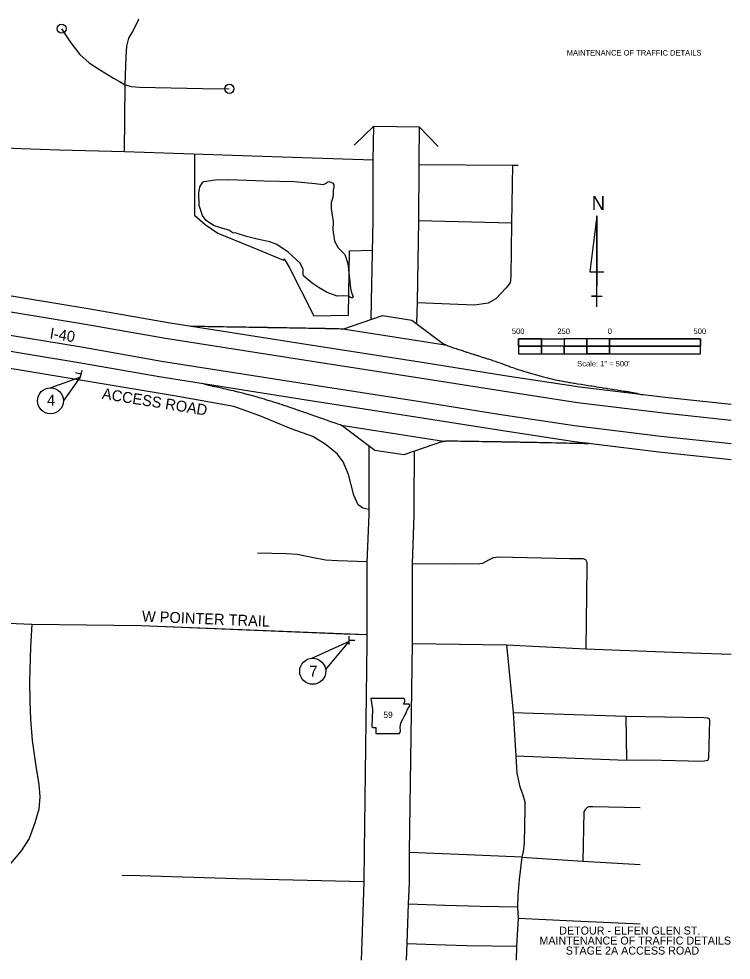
# Model space of a CAD drawing. Extents: x 185625 to 193575, y 1257500 to 1262681.
# Drawn here: x 189658 to 193575, y 1257500 to 1262681 of the extents above; entities that cross this region are included whole.
import ezdxf

# ---------------------------------------------------------------- set-up
doc = ezdxf.new("R2010")
doc.units = 0
for name, color, linetype in [('10', 7, 'Continuous'), ('21', 7, 'Continuous'), ('35', 7, 'Continuous'), ('37', 7, 'Continuous'), ('8', 7, 'Continuous'), ('Level 1', 7, 'Continuous'), ('Level 3', 7, 'Continuous'), ('Level 32', 7, 'Continuous'), ('Level 8', 7, 'Continuous')]:
    doc.layers.add(name, color=color, linetype=linetype)

msp = doc.modelspace()

# ---------------------------------------------------------------- linework, layer by layer
at = {"layer": '10'}
for p, q in [((191440.1, 1260972.6), (191658.4, 1261048)), ((191658.4, 1261048), (191818.5, 1261023.1)), ((191818.5, 1261023.1), (192003.6, 1260885)), ((191721.8, 1260928.8), (191440.1, 1260972.6)), ((192003.6, 1260885), (191721.8, 1260928.8)), ((191615.5, 1260305.5), (191430.5, 1260443.8)), ((191430.5, 1260443.8), (191712.2, 1260399.8)), ((191712.2, 1260399.8), (191993.9, 1260355.8)), ((191993.9, 1260355.8), (191775.6, 1260280.5)), ((191775.6, 1260280.5), (191615.5, 1260305.5))]:
    msp.add_line(p, q, dxfattribs=at)
for points in [[(190239.8, 1261948.5), (190243, 1262317.6), (190247.8, 1262473.6), (190252.5, 1262530.8), (190263.7, 1262573.8), (190284.3, 1262610.4), (190316.2, 1262675.6), (190317.7, 1262680.7)], [(189893.1, 1262626.3), (189944, 1262548.3), (189993.3, 1262484.7), (190045.8, 1262438.6), (190107.8, 1262398.8), (190179.4, 1262354.2), (190211.2, 1262335.1), (190243, 1262317.6)], [(190243, 1262317.6), (190276.4, 1262308.1), (190320.9, 1262304.9), (190667.7, 1262297), (190815.6, 1262295.4)], [(191596.5, 1261026.6), (191598.3, 1261127.6), (191606.9, 1261572), (191607.2, 1261878.7), (191607.1, 1261898.5), (191610.2, 1262090.1)], [(191610.2, 1262090.1), (191860.2, 1262086), (191857.1, 1261897.5), (191857.2, 1261879.7), (191856.9, 1261569.5), (191848.3, 1261122.6), (191845.8, 1261002.7)], [(191607.1, 1261902.2), (190996, 1261923), (190239.8, 1261948.5), (189882, 1261957.3), (189673.6, 1261965.3), (189185.3, 1261986), (188879.9, 1261994.5), (188779.5, 1261996.5), (188563.3, 1262000.1), (188150.6, 1262010.8)], [(190623.5, 1261935.6), (190624.8, 1261599.6), (190682.4, 1261548), (190752.3, 1261501.3), (190973.2, 1261410.5), (191113, 1261352.8), (191116.7, 1261360.2), (191144.9, 1261314.7), (191280.6, 1261046.2), (191471.6, 1261050.4), (191477.4, 1261403.8)], [(192373.6, 1261875.3), (192368.3, 1261555.8), (192364.7, 1261262.5), (192359.3, 1261228.6), (192337.9, 1261200), (192280.7, 1261139.2), (192239.6, 1261116), (192164.6, 1261105.3), (191848.2, 1261118.4)], [(191857.2, 1261878.4), (192373.6, 1261875.3), (192404, 1261875.3)], [(193575.5, 1260557.6), (193212.7, 1260596.5), (192742.7, 1260653.6), (192330.9, 1260716.5), (191888.1, 1260787.1), (191307.8, 1260876.8), (190478.8, 1261007.5), (190038.6, 1261084.8), (189048.5, 1261248.2), (187820.3, 1261444.8), (186840.7, 1261603.3)], [(192368.3, 1261555.8), (191856.9, 1261568.5)], [(186840.7, 1261517.2), (187806.8, 1261360.9), (189034.8, 1261164.3), (190024.3, 1261001), (190464.9, 1260923.6), (191294.7, 1260792.9), (191874.9, 1260703.1), (192317.8, 1260632.5), (192731.2, 1260569.4), (193203.1, 1260512.1), (193575.5, 1260472.1)], [(193575.5, 1260341.4), (193188.3, 1260382.9), (192713.5, 1260440.6), (192297.7, 1260504), (191854.7, 1260574.7), (191274.6, 1260664.4), (190443.5, 1260795.4), (190002.5, 1260872.9), (189014, 1261035.9), (187786.1, 1261232.6), (186840.7, 1261385.5)], [(191477.4, 1261403.8), (191603.8, 1261408.2), (191603.8, 1261408.2)], [(186840.7, 1261299.4), (187772.6, 1261148.7), (189000.3, 1260952), (189988.2, 1260789.1), (190429.5, 1260711.5), (191261.5, 1260580.4), (191841.6, 1260490.7), (192284.6, 1260420), (192702, 1260356.4), (193178.6, 1260298.5), (193575.5, 1260255.9)], [(191582.4, 1259981.2), (191550.8, 1259987.2), (191524.3, 1260006.5), (191500.2, 1260059.6), (191471.2, 1260173), (191442.3, 1260243), (191410.9, 1260284), (191348.2, 1260337.1), (191275.8, 1260382.9), (191155.2, 1260424), (190983.1, 1260495.9), (190840.8, 1260546.5), (190511.6, 1260605.2), (189655.3, 1260749.8), (189036.5, 1260848.7), (188221.1, 1260983.9), (187505.6, 1261095.4), (186840.7, 1261207.7)], [(191443.4, 1260973.7), (191443.3, 1260973.7), (191439.8, 1260973.5), (191432.4, 1260973.6), (191427.9, 1260973.7), (191418.1, 1260974.1), (191407.8, 1260974.5), (191402.2, 1260974.6), (191387.2, 1260974.9), (191372.1, 1260975.1), (191364.6, 1260975.3), (191356.9, 1260975.4), (191344.6, 1260975.5), (191342.1, 1260975.6), (191327.1, 1260975.9), (191324.7, 1260975.9), (191312.1, 1260976.1), (191297.2, 1260976.4), (191282.2, 1260976.7), (191267.1, 1260977), (191252, 1260977.3), (191237, 1260977.5), (191222, 1260977.8), (191192, 1260978.3), (191184.7, 1260978.4), (191177.4, 1260978.5), (191162.3, 1260978.9), (191147.1, 1260979.1), (191132.1, 1260979.3), (191117.3, 1260979.5), (191102.3, 1260979.8), (191087.3, 1260980.1), (191084.8, 1260980.2), (191064.6, 1260980.5), (191057, 1260980.5), (191044.8, 1260980.7), (191042.3, 1260980.7), (191027.4, 1260981), (191024.9, 1260981.1), (191012.3, 1260981.3), (190997.3, 1260981.6), (190982.2, 1260981.8), (190967.1, 1260982.1), (190963.7, 1260982.1), (190952.1, 1260982.2), (190937.2, 1260982.5), (190923.8, 1260982.7), (190907.1, 1260982.9), (190903.7, 1260982.9), (190892.1, 1260983.1), (190877.2, 1260983.3), (190863.8, 1260983.5), (190862.3, 1260983.5), (190832.3, 1260984), (190817.3, 1260984.3), (190802.5, 1260984.5), (190783.1, 1260985), (190772.3, 1260985.2), (190762.9, 1260985.4), (190757.4, 1260985.5), (190742.9, 1260985.7), (190742.2, 1260985.7), (190722.8, 1260986), (190712.3, 1260986.2), (190702.8, 1260986.3), (190697.2, 1260986.4), (190682.3, 1260986.7), (190667.3, 1260987), (190652.1, 1260987.2), (190637.1, 1260987.4), (190622.7, 1260987.6), (190607.1, 1260987.8), (190606.4, 1260987.8), (190603.6, 1260987.8)], [(191992.2, 1260893.4), (191997.2, 1260890.5), (191998.8, 1260889.5), (192006.2, 1260885.7), (192017.7, 1260881.1), (192033.4, 1260875.4), (192046.9, 1260870.7), (192048.6, 1260870.1), (192062.9, 1260865.5), (192067.6, 1260863.9), (192077.6, 1260860.8), (192091.7, 1260856.3), (192105.6, 1260851.7), (192106.1, 1260851.6), (192120.4, 1260847), (192124.8, 1260845.7), (192143.7, 1260839.6), (192162.7, 1260833.4), (192163.5, 1260833.2), (192177.8, 1260828.6), (192181.8, 1260827.3), (192200.9, 1260821.2), (192219.8, 1260815.2), (192220.5, 1260815), (192234.7, 1260810.4), (192238.6, 1260809.1), (192262.1, 1260801.3), (192262.9, 1260801.1), (192276.9, 1260796.4), (192290.7, 1260791.6), (192304.5, 1260786.7), (192317.7, 1260781.9), (192318.6, 1260781.6), (192332.7, 1260776.5), (192336.7, 1260775.1), (192355.5, 1260768.3), (192361, 1260766.3), (192375.5, 1260761.2), (192393.9, 1260754.9), (192404.2, 1260751.4), (192418.7, 1260746.5), (192432.7, 1260742), (192433.9, 1260741.6), (192447.9, 1260737.3), (192452.2, 1260736), (192472.9, 1260730), (192477.7, 1260728.7), (192492.1, 1260724.6), (192492.2, 1260724.6), (192511.4, 1260719.2), (192531, 1260713.7), (192535.9, 1260712.4), (192550.6, 1260708.4), (192565.5, 1260704.7), (192570.7, 1260703.3), (192580.5, 1260701), (192590.1, 1260698.6), (192595.1, 1260697.5), (192609.7, 1260694.2), (192610.5, 1260694), (192625.6, 1260691), (192630.7, 1260690), (192640.3, 1260688.1), (192650.7, 1260686), (192655.9, 1260685.1), (192670.7, 1260682.5), (192671, 1260682.5), (192685.4, 1260680), (192690.7, 1260679.1), (192700.6, 1260677.5), (192710.7, 1260675.8), (192715.5, 1260675), (192730.4, 1260672.6), (192730.6, 1260672.6), (192750.3, 1260669.5), (192759.9, 1260667.9), (192770.1, 1260666.3), (192789.8, 1260663.2), (192790, 1260663.2), (192804.6, 1260660.9), (192809.8, 1260660.1), (192819.5, 1260658.6), (192829.5, 1260657), (192834.1, 1260656.3), (192848.9, 1260653.9), (192849.2, 1260653.9), (192863.9, 1260651.6), (192868.9, 1260650.8), (192888.6, 1260647.7), (192893.4, 1260646.9), (192908.2, 1260644.6), (192923.1, 1260642.2), (192928.2, 1260641.4), (192948, 1260638.4), (192952.7, 1260637.6), (192967.4, 1260635.3), (192967.6, 1260635.3), (192987.5, 1260632.2), (192997.1, 1260630.7), (193007.2, 1260629.1), (193012, 1260628.3), (193017.1, 1260627.5), (193047.3, 1260622.8), (193056, 1260621.3), (193066.5, 1260617.8), (193087.4, 1260611.8), (193087.6, 1260611.7)], [(191433.3, 1260442.4), (191432.8, 1260442.6), (191430.6, 1260443.5), (191425.9, 1260445.4), (191411.7, 1260450.6), (191393.3, 1260457), (191390.2, 1260458), (191374.5, 1260463.4), (191355.3, 1260469.9), (191336.3, 1260476.7), (191319.2, 1260482.6), (191317.8, 1260483.1), (191305.3, 1260487.4), (191298.7, 1260489.6), (191279.6, 1260496.4), (191276.5, 1260497.5), (191260.7, 1260503), (191241.7, 1260509.8), (191233.8, 1260512.6), (191222.9, 1260516.5), (191220, 1260517.5), (191205.9, 1260522.4), (191204.3, 1260523), (191191.8, 1260527.4), (191185.5, 1260529.6), (191177.7, 1260532.2), (191166.8, 1260536), (191148, 1260542.4), (191135.3, 1260546.8), (191129.1, 1260548.9), (191110.4, 1260555.2), (191107.5, 1260556.2), (191093.2, 1260560.9), (191092.1, 1260561.3), (191073.2, 1260567.1), (191064.9, 1260569.8), (191054.2, 1260573.3), (191051.6, 1260574.1), (191037.2, 1260578.5), (191035.7, 1260578.9), (191016.8, 1260584.6), (191009, 1260586.9), (190994.8, 1260591), (190994.7, 1260591.1), (190980.6, 1260595.2), (190976.2, 1260596.5), (190957.5, 1260601.8), (190938.4, 1260606.9), (190938.3, 1260606.9), (190923.8, 1260610.8), (190919.1, 1260612.1), (190900.1, 1260617.2), (190895.4, 1260618.4), (190881.2, 1260622.1), (190866.7, 1260625.7), (190862.2, 1260626.9), (190843.3, 1260631.4), (190838.5, 1260632.6), (190823.9, 1260636), (190823.7, 1260636), (190809.3, 1260639.5), (190804.6, 1260640.6), (190794.9, 1260642.8), (190785.2, 1260645.1), (190780.3, 1260646.2), (190765.9, 1260649.6), (190751.2, 1260652.9), (190746.9, 1260653.9), (190737.4, 1260655.9), (190727.5, 1260658.1), (190707.7, 1260662.4), (190703.4, 1260663.4), (190683.9, 1260667.6), (190679.4, 1260669.2), (190665.5, 1260674.4)], [(191985.1, 1260353), (191985.2, 1260353.1), (191989.4, 1260354.6), (191994.5, 1260355.8), (191999.8, 1260356.7), (192003.1, 1260357.1), (192007.3, 1260357.5), (192014.8, 1260358), (192033.5, 1260358.1), (192047.4, 1260358), (192056.7, 1260357.9), (192066.9, 1260357.6), (192071.5, 1260357.5), (192086.5, 1260357.2), (192087.1, 1260357.2), (192102.1, 1260357), (192107.4, 1260356.9), (192117.1, 1260356.8), (192127.6, 1260356.7), (192132.4, 1260356.6), (192147.4, 1260356.5), (192147.5, 1260356.5), (192167.2, 1260356.2), (192176.7, 1260356), (192187, 1260355.7), (192206.7, 1260355.3), (192207.2, 1260355.3), (192222, 1260355.1), (192227.3, 1260355), (192237.1, 1260354.8), (192247.3, 1260354.7), (192266.9, 1260354.3), (192267.3, 1260354.3), (192282.1, 1260354.1), (192287.3, 1260354.1), (192307.2, 1260353.7), (192311.9, 1260353.6), (192323.7, 1260353.4), (192326.8, 1260353.3), (192330.2, 1260353.3), (192350.3, 1260353), (192372, 1260352.7), (192387, 1260352.4), (192390, 1260352.4), (192409.9, 1260351.9), (192416.8, 1260351.8), (192430.3, 1260351.6), (192432.3, 1260351.6), (192441.5, 1260351.5), (192447.1, 1260351.4), (192448.3, 1260351.4), (192468.1, 1260351), (192476.7, 1260350.8), (192488.1, 1260350.5), (192491.8, 1260350.5), (192507.9, 1260350.2), (192521.3, 1260349.8), (192527.9, 1260349.6), (192548, 1260349.2), (192566.5, 1260348.8), (192568, 1260348.7), (192581.6, 1260348.5), (192588, 1260348.3), (192610.7, 1260347.8), (192611.5, 1260347.8), (192626.2, 1260347.5), (192630.3, 1260347.4), (192641.1, 1260347.1), (192650.2, 1260346.9), (192670.6, 1260346.4), (192671.8, 1260346.4), (192686.8, 1260346.2), (192690.7, 1260346.2), (192701.3, 1260346), (192710.4, 1260345.8), (192716.3, 1260345.7), (192730.3, 1260345.4), (192731, 1260345.4), (192746, 1260345), (192750, 1260344.9), (192760.7, 1260344.5), (192769.8, 1260344.2), (192789.3, 1260344.4), (192790.1, 1260344.5), (192793.8, 1260345.2)], [(191583.8, 1260329.2), (191582.5, 1260020.3), (191582.4, 1259952.4), (191572.1, 1259686.1), (191572.7, 1259287.3), (191572.8, 1259244.8), (191557.4, 1258099.4), (191555.8, 1257931.1), (191551.7, 1257819.4), (191544, 1257602.7), (191540.1, 1257500.1)], [(191790.2, 1257500.1), (191793.8, 1257593.5), (191801.6, 1257810.3), (191805.8, 1257925.3), (191807.4, 1258096.6), (191822.8, 1259243.4), (191822.7, 1259287.8), (191822.2, 1259681.4), (191832.4, 1259947.4), (191832.5, 1260019.6), (191833.7, 1260300.6)], [(191572.4, 1259692.4), (191412.3, 1259697), (191344.7, 1259701.8), (191269.1, 1259716.3), (191188.7, 1259732.4), (191127.6, 1259737.2), (190970, 1259740.4)], [(191822.2, 1259683.2), (192051.4, 1259682.1), (192192.5, 1259683.3), (192210.6, 1259685.7), (192242, 1259703.8), (192268.5, 1259715.9), (192297.4, 1259719.5), (192687, 1259709.8), (192759.3, 1259709.8), (192773.8, 1259705), (192781, 1259690.5), (192782.2, 1259665.2), (192776.2, 1259212.7)], [(189249.2, 1259369.2), (189730.5, 1259348.6), (190331.7, 1259341.3), (191444.9, 1259295.9), (191572.7, 1259291.7)], [(189730.5, 1259348.6), (189722.5, 1259223.2), (189717.2, 1259035.2), (189718.5, 1258923.1), (189722.5, 1258827.1), (189731.8, 1258709.8), (189751.8, 1258568.4), (189767.8, 1258466.5), (189773.2, 1258399.8), (189767.8, 1258330.5), (189746.5, 1258255.8), (189715.8, 1258169.1), (189671.8, 1258101.1), (189531.9, 1257938.4)], [(191822.8, 1259242.3), (192339.5, 1259234.7), (192776.2, 1259212.7), (193255.1, 1259195.8), (193357.5, 1259191.7), (193575.5, 1259183.3)], [(192339.5, 1259234.7), (192377.1, 1258863), (192391.4, 1258622.1), (192396.2, 1258530.1), (192413.5, 1258454.9), (192429, 1258410.6), (192440.5, 1258370.7), (192440.5, 1258335.4), (192437.6, 1258146.2), (192430.9, 1258098), (192424.5, 1258067.4), (192409.7, 1257943.8), (192402.9, 1257856.1), (192401, 1257794.5), (192404.9, 1257730.9), (192394.3, 1257576.9), (192393.4, 1257500.1)], [(192377.1, 1258863), (192712.4, 1258851.4), (192996.5, 1258843.7), (193424.6, 1258836), (193446.8, 1258833.1), (193454.5, 1258827.4), (193456.4, 1258820.6), (193451.6, 1258611.5), (193447.7, 1258599.9), (193438.1, 1258597.1), (193416.9, 1258594.2), (193192.5, 1258599.9), (193106.1, 1258600.9), (192999.2, 1258599.9), (192716.9, 1258610.7), (192391.4, 1258622.1)], [(192996.5, 1258843.7), (192999.2, 1258599.9)], [(193075.9, 1258338.3), (192814.4, 1258344.6), (192791.6, 1258344.6), (192783, 1258340.3), (192774.4, 1258331.7), (192765.9, 1258316), (192760.1, 1258044.6)], [(192424.5, 1258067.4), (192123.4, 1258079.8), (191807.4, 1258092.9)], [(192424.5, 1258067.4), (192760.1, 1258044.6), (193075.9, 1258027)], [(191555.8, 1257931), (190855.6, 1257946.9), (190324, 1257963.8), (190227.1, 1257966.9)], [(191801.5, 1257810), (192001.3, 1257802.3), (192195.8, 1257797.5), (192401, 1257794.5)], [(192404.9, 1257730.9), (192708.8, 1257716.6), (193075.9, 1257700.9)], [(191793.8, 1257592.5), (191948.3, 1257585.6), (192121.7, 1257580.8), (192394.3, 1257576.9)]]:
    msp.add_lwpolyline(points, dxfattribs=at)
for centre in [(189893.1, 1262626.3), (190815.6, 1262295.4)]:
    msp.add_circle(centre, 25, dxfattribs=at)
at = {"layer": '21'}
msp.add_lwpolyline([(191593.6, 1258940.1), (191602.8, 1258878.8), (191598.6, 1258785.8), (191606.8, 1258780.7), (191622.1, 1258780.7), (191622.1, 1258747.9), (191750.8, 1258747.8), (191757, 1258761.1), (191754.9, 1258782.6), (191758, 1258807.1), (191769.3, 1258826.5), (191776.4, 1258840.8), (191786.7, 1258856.1), (191792.8, 1258872.4), (191797.9, 1258885.7), (191807.2, 1258897), (191809.2, 1258904.1), (191805.1, 1258909.2), (191773.4, 1258909.2), (191780.6, 1258923.5), (191781.6, 1258932.8), (191777.4, 1258939.8)], close=True, dxfattribs=at)
at = {"layer": '35'}
for points in [[(190853.6, 1261500.5), (190834.5, 1261503.7), (190813.8, 1261518), (190780.4, 1261525.9), (190729.5, 1261543.4), (190688.2, 1261570.5), (190667.5, 1261599.1), (190650, 1261653.2), (190648.4, 1261721.6), (190653.2, 1261756.6), (190670.7, 1261782.1), (190677, 1261785.3), (190737.5, 1261794.8), (190813.8, 1261796.4), (191007.9, 1261790), (191173.3, 1261785.3), (191287.8, 1261774.1), (191333.9, 1261769.4), (191351.4, 1261778.9), (191357.8, 1261783.7), (191362.5, 1261785.3), (191373.7, 1261782.1), (191384.8, 1261775.7), (191391.2, 1261766.2), (191391.2, 1261753.5), (191386.4, 1261737.5), (191386.4, 1261718.4), (191384.8, 1261697.8), (191375.3, 1261669.1), (191375.3, 1261637.3), (191386.4, 1261564.1), (191384.8, 1261519.6)], [(191384.8, 1261519.6), (191394.3, 1261457.5), (191415, 1261420.9), (191451.6, 1261384.3), (191467.5, 1261335), (191481.8, 1261198.2), (191489.8, 1261166.4), (191496.1, 1261155.2), (191491.4, 1261145.7), (191488.2, 1261145.7), (191470.7, 1261155.2), (191445.2, 1261156.8), (191408.7, 1261155.2), (191354.6, 1261174.3), (191310.1, 1261199.8), (191271.9, 1261225.2), (191238.5, 1261253.9), (191224.2, 1261266.6), (191222.6, 1261276.1), (191222.6, 1261301.6), (191205.1, 1261336.6), (191139.9, 1261397.1), (191077.8, 1261438.4), (191038.1, 1261454.3), (190969.7, 1261468.7), (190910.8, 1261483), (190853.6, 1261500.5)]]:
    msp.add_lwpolyline(points, dxfattribs=at)
at = {"layer": '37'}
for points in [[(191502.4, 1261985.8), (191610.2, 1262090.1)], [(191860.2, 1262086), (191964.5, 1261978.2)]]:
    msp.add_lwpolyline(points, dxfattribs=at)
at = {"layer": 'Level 1'}
for p, q in [((192836.4, 1261596.3), (192798, 1261288.6)), ((192836.4, 1261096.3), (192836.4, 1261596.3)), ((192836.4, 1261596.3), (192836.4, 1261211.7)), ((192798, 1261288.6), (192874.9, 1261288.6)), ((192836.4, 1261096.3), (192836.4, 1261211.7)), ((192836.4, 1261154), (192807.6, 1261154)), ((192807.6, 1261154), (192865.3, 1261154)), ((192836.4, 1261096.3), (192836.4, 1261154))]:
    msp.add_line(p, q, dxfattribs=at)
at = {"layer": 'Level 3'}
for p, q in [((189998.4, 1260724.4), (189968.9, 1260732.9)), ((190005.2, 1260745.8), (189992.8, 1260702.5)), ((191475.1, 1259238.2), (191475.1, 1259283.2)), ((191475.7, 1259260.6), (191506.5, 1259260.6))]:
    msp.add_line(p, q, dxfattribs=at)
at = {"layer": 'Level 32'}
for points in [[(192406.7, 1260920.5), (192531.7, 1260920.5), (192531.7, 1260878.9), (192406.7, 1260878.9)], [(192531.7, 1260920.5), (192656.7, 1260920.5), (192656.7, 1260878.9), (192531.7, 1260878.9)], [(192656.7, 1260878.9), (192781.7, 1260878.9), (192781.7, 1260920.5), (192656.7, 1260920.5)], [(192781.7, 1260878.9), (192906.7, 1260878.9), (192906.7, 1260920.5), (192781.7, 1260920.5)], [(192906.7, 1260920.5), (193406.7, 1260920.5), (193406.7, 1260878.9), (192906.7, 1260878.9)], [(192531.7, 1260878.9), (192406.7, 1260878.9), (192406.7, 1260837.2), (192531.7, 1260837.2)], [(192531.7, 1260837.2), (192656.7, 1260837.2), (192656.7, 1260878.9), (192531.7, 1260878.9)], [(192781.7, 1260878.9), (192656.7, 1260878.9), (192656.7, 1260837.2), (192781.7, 1260837.2)], [(192781.7, 1260878.9), (192906.7, 1260878.9), (192906.7, 1260837.2), (192781.7, 1260837.2)], [(193406.7, 1260878.9), (192906.7, 1260878.9), (192906.7, 1260837.2), (193406.7, 1260837.2)]]:
    msp.add_lwpolyline(points, close=True, dxfattribs=at)
for points in [[(192531.7, 1260878.9), (192531.7, 1260920.5), (192406.7, 1260920.5), (192406.7, 1260878.9), (192531.7, 1260878.9)], [(192656.7, 1260878.9), (192781.7, 1260878.9), (192781.7, 1260920.5), (192656.7, 1260920.5), (192656.7, 1260878.9)], [(192906.7, 1260920.5), (192906.7, 1260878.9), (193406.7, 1260878.9), (193406.7, 1260920.5), (192906.7, 1260920.5)], [(192656.7, 1260837.2), (192656.7, 1260878.9), (192531.7, 1260878.9), (192531.7, 1260837.2), (192656.7, 1260837.2)], [(192781.7, 1260837.2), (192906.7, 1260837.2), (192906.7, 1260878.9), (192781.7, 1260878.9), (192781.7, 1260837.2)]]:
    msp.add_lwpolyline(points, dxfattribs=at)
at = {"layer": 'Level 8'}
for points in [[(189903.6, 1260576.3), (189997.1, 1260709.5), (189834.2, 1260650)], [(189249.2, 1259369.2), (189730.5, 1259348.6), (190331.7, 1259341.3), (191572.7, 1259291.7)], [(191345.4, 1259097.4), (191474.7, 1259254), (191266.9, 1259161.1)]]:
    msp.add_lwpolyline(points, dxfattribs=at)
for centre in [(189832.1, 1260578.5), (191274.3, 1259090)]:
    msp.add_circle(centre, 71.5, dxfattribs=at)

# ---------------------------------------------------------------- texts
at = {"layer": '8'}
msp.add_text('59', height=34.43, dxfattribs=at).set_placement((191663, 1258833))
at = {"layer": 'Level 1'}
msp.add_text('N', height=76.9, rotation=360, dxfattribs=at).set_placement((192808.3, 1261628.3))
at = {"layer": 'Level 32'}
for s, p in [('500', (192369.6, 1260946.3)), ('250', (192619.9, 1260946.3)), ('0', (192896.9, 1260946.3)), ('500', (193368.7, 1260946.3)), ('Scale: 1" = 500\'', (192728.8, 1260767.8))]:
    msp.add_text(s, height=30, dxfattribs=at).set_placement(p)
at = {"layer": 'Level 8'}
for s, height, p in [('MAINTENANCE OF TRAFFIC DETAILS', 30, (192671.1, 1262478.7)), ('4', 60, (189813.2, 1260552.4)), ('7', 60, (191255.9, 1259060.9)), ('DETOUR - ELFEN GLEN ST.', 44.047, (192630.1, 1257641.2)), ('MAINTENANCE OF TRAFFIC DETAILS', 44.047, (192521.1, 1257586)), ('STAGE 2A ACCESS ROAD', 44.047, (192666.1, 1257530.9))]:
    msp.add_text(s, height=height, dxfattribs=at).set_placement(p)
for s, rotation, p in [('I-40', 350.8389, (189825.3, 1260922.4)), ('ACCESS ROAD', 350.8389, (190112.4, 1260589.9)), ('W POINTER TRAIL', 357.6675, (190334.2, 1259363.6))]:
    msp.add_text(s, height=60, rotation=rotation, dxfattribs=at).set_placement(p)

doc.saveas('drawing.dxf')
